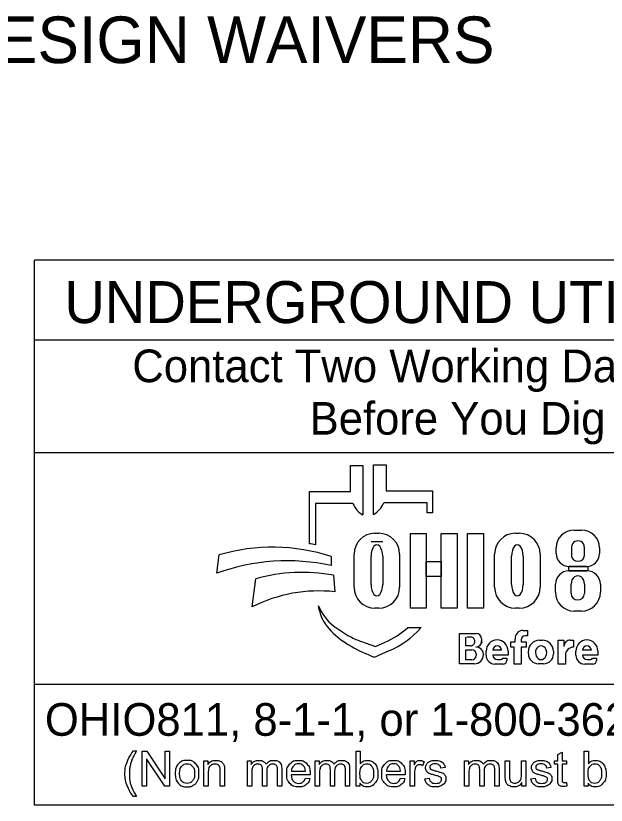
# Model space of a CAD drawing. Extents: x -10.5 to 40.6, y -3.2 to 22.
# Drawn here: x 2.897 to 5.431, y 2.143 to 5.529 of the extents above; entities that cross this region are included whole.
import ezdxf

# ---------------------------------------------------------------- set-up
doc = ezdxf.new("R2010")
doc.units = 0
doc.layers.add('SH_Data', color=7, linetype='Continuous')
doc.layers.add('SH_Text', color=7, linetype='Continuous')

msp = doc.modelspace()

# ---------------------------------------------------------------- linework, layer by layer
at = {"layer": 'SH_Data'}
for p, q in [((2.9775, 2.1428), (2.9775, 4.4803)), ((7.2275, 4.4803), (2.9775, 4.4803)), ((2.9775, 4.1387), (7.2275, 4.1387)), ((2.9775, 3.6553), (7.2275, 3.6553)), ((7.2275, 2.6607), (2.9775, 2.6607)), ((7.2275, 2.1428), (2.9775, 2.1428))]:
    msp.add_line(p, q, dxfattribs=at)
at = {"layer": 'SH_Text'}
for p, q in [((4.3335, 3.4883), (4.3335, 3.5998)), ((4.3335, 3.5998), (4.3872, 3.5998)), ((4.3872, 3.5998), (4.3872, 3.3877)), ((4.4329, 3.39), (4.4329, 3.6021)), ((4.4329, 3.6021), (4.4865, 3.6021)), ((4.4865, 3.6021), (4.4865, 3.4906)), ((4.1576, 3.2644), (4.1576, 3.4883)), ((4.1576, 3.4883), (4.3335, 3.4883)), ((4.4865, 3.4906), (4.6857, 3.4906)), ((4.6857, 3.4906), (4.6857, 3.3968)), ((4.1828, 3.4369), (4.1828, 3.26)), ((4.3439, 3.4369), (4.1828, 3.4369)), ((4.6625, 3.4392), (4.4761, 3.4392)), ((4.6625, 3.3968), (4.6625, 3.4392)), ((4.6857, 3.3968), (4.6625, 3.3968)), ((5.2931, 3.3231), (5.3258, 3.3231)), ((4.4385, 3.3091), (4.4551, 3.3091)), ((5.0416, 3.3091), (5.0581, 3.3091)), ((4.4718, 3.2721), (4.422, 3.2721)), ((5.283, 3.2111), (5.283, 3.2504)), ((5.3371, 3.2504), (5.3371, 3.2111)), ((4.3491, 3.0776), (4.3491, 3.2196)), ((4.5445, 3.2196), (4.5445, 3.0776)), ((4.9521, 3.0776), (4.9521, 3.2196)), ((5.1476, 3.2196), (5.1476, 3.0776)), ((5.2168, 3.2225), (5.2168, 3.2468)), ((5.4022, 3.2468), (5.4022, 3.2225)), ((3.7602, 3.1381), (3.7696, 3.2162)), ((4.2509, 3.2097), (4.2509, 3.1709)), ((4.422, 3.089), (4.422, 3.2114)), ((4.4718, 3.2114), (4.4718, 3.089)), ((5.025, 3.089), (5.025, 3.2114)), ((5.0748, 3.2114), (5.0748, 3.089)), ((5.3462, 3.1665), (5.2728, 3.1665)), ((4.2608, 3.1291), (4.2671, 3.0582)), ((5.271, 3.1482), (5.3483, 3.1482)), ((3.912, 2.9936), (3.9267, 3.1137)), ((5.2131, 3.0563), (5.2131, 3.0903)), ((5.2806, 3.0503), (5.2806, 3.0912)), ((5.3374, 3.0912), (5.3374, 3.0503)), ((5.4062, 3.0903), (5.4062, 3.0563)), ((4.1997, 2.9807), (4.1967, 2.9986)), ((4.4551, 2.9882), (4.4385, 2.9882)), ((5.0581, 2.9882), (5.0416, 2.9882)), ((5.3252, 2.9753), (5.2941, 2.9753)), ((4.58, 2.9048), (4.6375, 2.9048)), ((4.8013, 2.749), (4.8013, 2.8798)), ((4.8013, 2.8798), (4.8725, 2.8798)), ((5.0739, 2.8926), (5.0934, 2.8926)), ((5.0934, 2.8926), (5.0934, 2.8696)), ((4.3816, 2.8444), (4.441, 2.8239)), ((4.8293, 2.8263), (4.8293, 2.8632)), ((4.8545, 2.8632), (4.8332, 2.8632)), ((4.8963, 2.856), (4.8963, 2.8481)), ((5.0213, 2.8212), (5.0213, 2.8442)), ((5.0213, 2.8442), (5.0406, 2.8442)), ((5.0406, 2.8442), (5.0406, 2.8546)), ((5.0667, 2.8526), (5.0667, 2.8442)), ((5.0667, 2.8442), (5.0883, 2.8442)), ((5.0934, 2.8691), (5.0832, 2.8691)), ((5.0883, 2.8442), (5.0883, 2.8212)), ((5.1451, 2.8508), (5.1573, 2.8508)), ((5.2254, 2.7478), (5.2254, 2.8505)), ((5.2254, 2.8505), (5.2499, 2.8505)), ((5.2499, 2.8505), (5.2499, 2.8237)), ((5.2772, 2.8505), (5.291, 2.8505)), ((5.291, 2.8505), (5.291, 2.8209)), ((4.441, 2.8239), (4.4821, 2.8417)), ((4.8487, 2.8263), (4.8293, 2.8263)), ((5.0362, 2.8212), (5.0213, 2.8212)), ((5.0362, 2.7478), (5.0362, 2.8212)), ((5.0883, 2.8212), (5.0667, 2.8212)), ((5.0667, 2.8212), (5.0667, 2.7478)), ((4.435, 2.7769), (4.3976, 2.7934)), ((4.4983, 2.8044), (4.435, 2.7769)), ((4.8293, 2.7669), (4.8293, 2.8097)), ((4.8293, 2.8097), (4.8548, 2.8097)), ((4.8729, 2.7916), (4.8729, 2.7853)), ((4.9043, 2.7887), (4.9043, 2.7884)), ((4.9159, 2.7858), (4.9159, 2.8042)), ((4.9824, 2.8082), (4.9439, 2.8082)), ((5.0104, 2.7866), (4.944, 2.7866)), ((5.0104, 2.8042), (5.0104, 2.7866)), ((5.0973, 2.7922), (5.0973, 2.8029)), ((5.2051, 2.8029), (5.2051, 2.7922)), ((5.2559, 2.786), (5.2559, 2.7478)), ((5.3008, 2.7858), (5.3008, 2.8042)), ((5.3674, 2.8082), (5.3288, 2.8082)), ((5.3953, 2.7866), (5.3289, 2.7866)), ((5.3953, 2.8042), (5.3953, 2.7866)), ((4.865, 2.749), (4.8013, 2.749)), ((4.8546, 2.7669), (4.8293, 2.7669)), ((4.9892, 2.7478), (4.9538, 2.7478)), ((4.9649, 2.7673), (4.979, 2.7673)), ((4.9876, 2.7729), (5.0045, 2.7729)), ((5.0045, 2.7729), (5.0045, 2.7631)), ((5.0667, 2.7478), (5.0362, 2.7478)), ((5.1623, 2.7494), (5.1401, 2.7494)), ((5.2559, 2.7478), (5.2254, 2.7478)), ((5.3742, 2.7478), (5.3388, 2.7478)), ((5.3498, 2.7673), (5.3639, 2.7673)), ((5.3725, 2.7729), (5.3894, 2.7729)), ((5.3894, 2.7729), (5.3894, 2.7631))]:
    msp.add_line(p, q, dxfattribs=at)
for points in [[(4.591, 3.3081), (4.6589, 3.3081), (4.6589, 2.9881), (4.591, 2.9881)], [(4.7231, 3.3081), (4.7911, 3.3081), (4.7911, 2.9881), (4.7231, 2.9881)], [(4.8364, 3.3081), (4.9052, 3.3081), (4.9052, 2.9881), (4.8364, 2.9881)], [(4.6589, 3.1882), (4.7231, 3.1882), (4.7231, 3.1242), (4.6589, 3.1242)], [(5.2706, 3.1665), (5.3523, 3.1665), (5.3523, 3.1481), (5.2706, 3.1481)]]:
    msp.add_lwpolyline(points, close=True, dxfattribs=at)
for points in [[(3.4021, 2.3766), (3.4153, 2.3766)], [(3.4389, 2.2239), (3.4389, 2.3741), (3.4592, 2.3741), (3.5382, 2.2561), (3.5382, 2.3741), (3.5572, 2.3741), (3.5572, 2.2239), (3.5369, 2.2239), (3.4579, 2.3419), (3.4579, 2.2239), (3.4389, 2.2239)], [(4.3743, 2.2239), (4.3573, 2.2239), (4.3573, 2.3741), (4.3757, 2.3741), (4.3757, 2.3206)], [(5.2233, 2.2558), (5.2233, 2.3185), (5.2097, 2.3185), (5.2097, 2.3328), (5.2233, 2.3328), (5.2233, 2.3597), (5.2417, 2.3708), (5.2417, 2.3328), (5.2601, 2.3328), (5.2601, 2.3185), (5.2417, 2.3185), (5.2417, 2.2547)], [(5.3534, 2.2239), (5.3363, 2.2239), (5.3363, 2.3741), (5.3548, 2.3741), (5.3548, 2.3206)], [(3.7048, 2.2239), (3.7048, 2.3328), (3.7214, 2.3328), (3.7214, 2.3173)], [(3.8912, 2.2239), (3.8912, 2.3328), (3.9077, 2.3328), (3.9077, 2.3174)], [(4.1826, 2.2239), (4.1826, 2.3328), (4.1991, 2.3328), (4.1991, 2.3174)], [(4.5904, 2.2239), (4.5904, 2.3328), (4.607, 2.3328), (4.607, 2.3163)], [(4.6495, 2.3293), (4.643, 2.3122)], [(4.7394, 2.3046), (4.7213, 2.3022)], [(4.8236, 2.2239), (4.8236, 2.3328), (4.8401, 2.3328), (4.8401, 2.3174)], [(4.9979, 2.2654), (4.9979, 2.3328), (5.0164, 2.3328), (5.0164, 2.2724)], [(5.0676, 2.2745), (5.0676, 2.3328), (5.0861, 2.3328), (5.0861, 2.2239), (5.0696, 2.2239)], [(5.194, 2.3046), (5.1759, 2.3022)], [(3.7233, 2.2833), (3.7233, 2.2239), (3.7048, 2.2239)], [(3.7932, 2.2908), (3.7932, 2.2239), (3.7748, 2.2239), (3.7748, 2.2901)], [(3.9097, 2.2803), (3.9097, 2.2239), (3.8912, 2.2239)], [(3.9743, 2.2871), (3.9743, 2.2239), (3.9559, 2.2239), (3.9559, 2.2946)], [(4.0388, 2.2986), (4.0388, 2.2239), (4.0203, 2.2239), (4.0203, 2.2924)], [(4.16, 2.2736), (4.0788, 2.2736)], [(4.0799, 2.2887), (4.1406, 2.2887)], [(4.201, 2.2803), (4.201, 2.2239), (4.1826, 2.2239)], [(4.2657, 2.2871), (4.2657, 2.2239), (4.2473, 2.2239), (4.2473, 2.2946)], [(4.3301, 2.2986), (4.3301, 2.2239), (4.3117, 2.2239), (4.3117, 2.2924)], [(4.568, 2.2736), (4.4868, 2.2736)], [(4.4879, 2.2887), (4.5486, 2.2887)], [(4.6088, 2.2809), (4.6088, 2.2239), (4.5904, 2.2239)], [(4.842, 2.2803), (4.842, 2.2239), (4.8236, 2.2239)], [(4.9067, 2.2871), (4.9067, 2.2239), (4.8883, 2.2239), (4.8883, 2.2946)], [(4.9711, 2.2986), (4.9711, 2.2239), (4.9527, 2.2239), (4.9527, 2.2924)], [(4.1404, 2.2591), (4.1595, 2.2567)], [(4.3743, 2.2375), (4.3743, 2.2239)], [(4.5484, 2.2591), (4.5675, 2.2567)], [(4.653, 2.2564), (4.6712, 2.2593)], [(5.0696, 2.2239), (5.0696, 2.24)], [(5.1076, 2.2564), (5.1258, 2.2593)], [(5.2601, 2.2404), (5.2628, 2.2241)], [(5.3534, 2.2375), (5.3534, 2.2239)], [(3.4153, 2.1798), (3.4021, 2.1798)]]:
    msp.add_lwpolyline(points, dxfattribs=at)
for centre, radius, start, end in [((4.4353, 3.4736), 0.0985, 201.9296, 240.7469), ((4.3847, 3.476), 0.0985, 299.2531, 338.0704), ((5.2931, 3.2468), 0.0763, 90, 180), ((5.3258, 3.2468), 0.0763, 0, 90), ((4.4385, 3.2196), 0.0895, 90, 180), ((4.4551, 3.2196), 0.0895, 0, 90), ((5.0416, 3.2196), 0.0895, 90, 180), ((5.0581, 3.2196), 0.0895, 0, 90), ((4.0295, 2.4554), 0.8191, 79.2074, 81.0007), ((3.9997, 2.4302), 0.8191, 72.1402, 106.3144), ((5.2728, 3.2225), 0.056, 180, 270), ((5.3462, 3.2225), 0.056, 270, 0), ((4.0628, 2.2991), 0.8919, 77.8238, 109.8274), ((4.1267, 2.4094), 0.7322, 79.44, 105.8467), ((5.271, 3.0903), 0.0579, 90, 180), ((5.3483, 3.0903), 0.0579, 0, 90), ((4.1987, 2.4262), 0.6357, 83.8248, 116.8021), ((4.4385, 3.0776), 0.0895, 180, 270), ((4.4551, 3.0776), 0.0895, 270, 0), ((5.0416, 3.0776), 0.0895, 180, 270), ((5.0581, 3.0776), 0.0895, 270, 0), ((5.2941, 3.0563), 0.081, 180, 270), ((5.3252, 3.0563), 0.081, 270, 0), ((4.3841, 3.0707), 0.2008, 201.0457, 232.5314), ((4.341, 3.0048), 0.1433, 189.6817, 216.0884), ((4.4747, 3.1022), 0.3088, 216.0884, 235.7167), ((4.5766, 3.3219), 0.5173, 232.5314, 241.794), ((4.3387, 3.1722), 0.3602, 293.4582, 312.0712), ((4.3387, 3.1722), 0.401, 293.4582, 317.8286), ((4.8725, 2.856), 0.0238, 0, 90), ((5.0739, 2.859), 0.0335, 90, 187.5187), ((4.6412, 3.3465), 0.6044, 235.7167, 246.2325), ((4.4914, 3.1631), 0.3371, 241.794, 250.9821), ((4.8487, 2.845), 0.0187, 270, 2.0582), ((4.8505, 2.8463), 0.0169, 357.8325, 90), ((4.8721, 2.8453), 0.0243, 270, 6.6529), ((4.9631, 2.8042), 0.0473, 0, 180), ((5.0832, 2.8526), 0.0165, 90, 180), ((5.1451, 2.8029), 0.0478, 90, 180), ((5.1573, 2.8029), 0.0478, 0, 90), ((5.2768, 2.8237), 0.0269, 89.2449, 180), ((5.3481, 2.8042), 0.0473, 0, 180), ((4.8722, 2.7889), 0.0321, 4.0748, 90), ((4.8827, 2.8438), 0.0175, 347.4023, 0), ((4.9632, 2.8072), 0.0193, 2.9632, 177.0368), ((5.2908, 2.786), 0.0349, 89.6033, 180), ((5.3481, 2.8072), 0.0193, 2.9632, 177.0368), ((4.8546, 2.7853), 0.0184, 270, 0), ((4.8548, 2.7916), 0.0181, 0, 90), ((4.865, 2.7884), 0.0393, 270, 0), ((4.8714, 2.7887), 0.033, 0, 11.7502), ((4.9538, 2.7858), 0.038, 180, 270), ((4.9649, 2.7883), 0.021, 184.827, 270), ((5.1401, 2.7922), 0.0428, 180, 270), ((5.1623, 2.7922), 0.0428, 270, 0), ((5.3388, 2.7858), 0.038, 180, 270), ((5.3498, 2.7883), 0.021, 184.827, 270), ((4.979, 2.7767), 0.00938, 270, 335.9979), ((4.9892, 2.7631), 0.0152, 270, 0), ((5.3639, 2.7767), 0.00938, 270, 335.9979), ((5.3742, 2.7631), 0.0152, 270, 0)]:
    msp.add_arc(centre, radius, start, end, dxfattribs=at)
for centre, major_axis, ratio, start_param, end_param in [((4.4469, 3.2114), (0, 0.0484), 0.514403, 4.712389, 7.853982), ((5.0499, 3.2114), (0, 0.0484), 0.514403, 4.712389, 7.853982), ((5.31, 3.2504), (0.0271, 0), 0.969373, 0, 3.141593), ((5.31, 3.2111), (0.0271, 0), 0.818453, 3.141593, 6.283185), ((5.309, 3.0912), (0, 0.0358), 0.794529, 4.712389, 7.853982), ((4.4469, 3.089), (0, 0.0484), 0.514403, 1.570796, 4.712389), ((5.0499, 3.089), (0, 0.0484), 0.514403, 1.570796, 4.712389), ((5.309, 3.0503), (0.0284, 0), 0.959837, 3.141593, 6.283185), ((5.1517, 2.7976), (0, 0.029), 0.832186, 4.712389, 7.853982), ((5.1517, 2.7976), (0, 0.0302), 0.797287, 1.570796, 4.712389)]:
    msp.add_ellipse(centre, major_axis=major_axis, ratio=ratio, start_param=start_param, end_param=end_param, dxfattribs=at)
for points in [[(3.4021, 2.1798), (3.3869, 2.199), (3.3763, 2.2248), (3.3657, 2.2506), (3.3657, 2.2783), (3.3657, 2.3026), (3.3736, 2.325), (3.3829, 2.3509), (3.4021, 2.3766)], [(3.4153, 2.3766), (3.4029, 2.3553), (3.3989, 2.3462), (3.3927, 2.332), (3.3891, 2.3167), (3.3847, 2.2975), (3.3847, 2.2782), (3.3847, 2.2289), (3.4153, 2.1798)], [(3.5814, 2.2783), (3.5814, 2.3085), (3.5981, 2.3231), (3.6122, 2.3352), (3.6323, 2.3352), (3.6547, 2.3352), (3.669, 2.3205), (3.6832, 2.3058), (3.6832, 2.2799), (3.6832, 2.2589), (3.6769, 2.2469), (3.6706, 2.2348), (3.6586, 2.2282), (3.6466, 2.2215), (3.6323, 2.2215), (3.6095, 2.2215), (3.5954, 2.2362), (3.5814, 2.2508), (3.5814, 2.2783)], [(3.6003, 2.2783), (3.6003, 2.2574), (3.6094, 2.247), (3.6185, 2.2366), (3.6323, 2.2366), (3.646, 2.2366), (3.6551, 2.2471), (3.6642, 2.2575), (3.6642, 2.279), (3.6642, 2.2991), (3.6551, 2.3095), (3.6459, 2.3199), (3.6323, 2.3199), (3.6185, 2.3199), (3.6094, 2.3096), (3.6003, 2.2992), (3.6003, 2.2783)], [(3.7214, 2.3173), (3.7334, 2.3352), (3.756, 2.3352), (3.7659, 2.3352), (3.7741, 2.3316), (3.7823, 2.3281), (3.7864, 2.3224), (3.7905, 2.3166), (3.7922, 2.3087), (3.7932, 2.3036), (3.7932, 2.2908)], [(3.7748, 2.2901), (3.7748, 2.3013), (3.7726, 2.3069), (3.7705, 2.3125), (3.765, 2.3158), (3.7595, 2.3191), (3.7521, 2.3191), (3.7404, 2.3191), (3.7318, 2.3117), (3.7233, 2.3042), (3.7233, 2.2833)], [(3.9077, 2.3174), (3.9128, 2.3254), (3.9214, 2.3303), (3.9299, 2.3352), (3.9407, 2.3352), (3.9528, 2.3352), (3.9606, 2.3301), (3.9683, 2.3251), (3.9715, 2.3161), (3.9844, 2.3352), (4.0051, 2.3352), (4.0213, 2.3352), (4.03, 2.3262), (4.0388, 2.3172), (4.0388, 2.2986)], [(3.9559, 2.2946), (3.9559, 2.3069), (3.9514, 2.313), (3.9469, 2.3191), (3.9366, 2.3191), (3.9288, 2.3191), (3.9222, 2.315), (3.9156, 2.311), (3.9126, 2.3031), (3.9097, 2.2952), (3.9097, 2.2803)], [(4.0203, 2.2924), (4.0203, 2.3035), (4.0185, 2.3083), (4.0168, 2.3132), (4.012, 2.3162), (4.0073, 2.3191), (4.001, 2.3191), (3.9895, 2.3191), (3.9819, 2.3115), (3.9743, 2.3039), (3.9743, 2.2871)], [(4.1595, 2.2567), (4.155, 2.24), (4.1428, 2.2307), (4.1306, 2.2215), (4.1117, 2.2215), (4.0878, 2.2215), (4.0738, 2.2362), (4.0598, 2.2509), (4.0598, 2.2774), (4.0598, 2.3049), (4.074, 2.32), (4.0881, 2.3352), (4.1106, 2.3352), (4.1324, 2.3352), (4.1463, 2.3203), (4.1601, 2.3055), (4.1601, 2.2785), (4.1601, 2.2769), (4.16, 2.2736)], [(4.1406, 2.2887), (4.1394, 2.3025), (4.1337, 2.3094), (4.1249, 2.3201), (4.1108, 2.3201), (4.0981, 2.3201), (4.0894, 2.3115), (4.0808, 2.303), (4.0799, 2.2887)], [(4.1991, 2.3174), (4.2042, 2.3254), (4.2127, 2.3303), (4.2212, 2.3352), (4.2321, 2.3352), (4.2442, 2.3352), (4.2519, 2.3301), (4.2597, 2.3251), (4.2628, 2.3161), (4.2758, 2.3352), (4.2965, 2.3352), (4.3127, 2.3352), (4.3214, 2.3262), (4.3301, 2.3172), (4.3301, 2.2986)], [(4.2473, 2.2946), (4.2473, 2.3069), (4.2428, 2.313), (4.2383, 2.3191), (4.228, 2.3191), (4.2202, 2.3191), (4.2136, 2.315), (4.207, 2.311), (4.204, 2.3031), (4.201, 2.2952), (4.201, 2.2803)], [(4.3117, 2.2924), (4.3117, 2.3035), (4.3099, 2.3083), (4.3081, 2.3132), (4.3034, 2.3162), (4.2987, 2.3191), (4.2923, 2.3191), (4.2809, 2.3191), (4.2733, 2.3115), (4.2657, 2.3039), (4.2657, 2.2871)], [(4.3741, 2.2792), (4.3741, 2.2596), (4.3794, 2.2509), (4.3881, 2.2366), (4.4029, 2.2366), (4.415, 2.2366), (4.4238, 2.2471), (4.4326, 2.2576), (4.4326, 2.2784), (4.4326, 2.2998), (4.4241, 2.3099), (4.4157, 2.3201), (4.4038, 2.3201), (4.3917, 2.3201), (4.3829, 2.3096), (4.3741, 2.299), (4.3741, 2.2792)], [(4.3757, 2.3206), (4.3874, 2.3352), (4.4055, 2.3352), (4.4155, 2.3352), (4.4245, 2.3311), (4.4335, 2.3271), (4.4392, 2.3198), (4.445, 2.3124), (4.4483, 2.3021), (4.4516, 2.2918), (4.4516, 2.28), (4.4516, 2.252), (4.4378, 2.2368), (4.4239, 2.2215), (4.4046, 2.2215), (4.3853, 2.2215), (4.3743, 2.2375)], [(4.5675, 2.2567), (4.563, 2.24), (4.5508, 2.2307), (4.5386, 2.2215), (4.5196, 2.2215), (4.4958, 2.2215), (4.4818, 2.2362), (4.4678, 2.2509), (4.4678, 2.2774), (4.4678, 2.3049), (4.482, 2.32), (4.4961, 2.3352), (4.5186, 2.3352), (4.5404, 2.3352), (4.5543, 2.3203), (4.5681, 2.3055), (4.5681, 2.2785), (4.5681, 2.2769), (4.568, 2.2736)], [(4.5486, 2.2887), (4.5474, 2.3025), (4.5417, 2.3094), (4.5328, 2.3201), (4.5188, 2.3201), (4.5061, 2.3201), (4.4974, 2.3115), (4.4888, 2.303), (4.4879, 2.2887)], [(4.607, 2.3163), (4.6133, 2.3278), (4.6187, 2.3315), (4.6241, 2.3352), (4.6305, 2.3352), (4.6398, 2.3352), (4.6495, 2.3293)], [(4.643, 2.3122), (4.6363, 2.3162), (4.6295, 2.3162), (4.6235, 2.3162), (4.6187, 2.3125), (4.6139, 2.3089), (4.6119, 2.3024), (4.6088, 2.2926), (4.6088, 2.2809)], [(4.7213, 2.3022), (4.7201, 2.3106), (4.7142, 2.3153), (4.7083, 2.3201), (4.6975, 2.3201), (4.6848, 2.3201), (4.6794, 2.3159), (4.6739, 2.3116), (4.6739, 2.306), (4.6739, 2.3024), (4.6762, 2.2995), (4.6785, 2.2966), (4.6833, 2.2946), (4.686, 2.2936), (4.6996, 2.2899), (4.7192, 2.2847), (4.7269, 2.2813), (4.7347, 2.278), (4.7391, 2.2717), (4.7435, 2.2653), (4.7435, 2.2559), (4.7435, 2.2467), (4.7381, 2.2386), (4.7327, 2.2304), (4.7226, 2.226), (4.7124, 2.2215), (4.6996, 2.2215), (4.6784, 2.2215), (4.6672, 2.2303), (4.6561, 2.2391), (4.653, 2.2564)], [(4.6712, 2.2593), (4.6727, 2.2483), (4.6798, 2.2425), (4.6868, 2.2366), (4.6995, 2.2366), (4.7122, 2.2366), (4.7184, 2.2418), (4.7245, 2.247), (4.7245, 2.254), (4.7245, 2.2602), (4.7191, 2.2638), (4.7153, 2.2663), (4.7002, 2.2701), (4.6799, 2.2752), (4.672, 2.2789), (4.6642, 2.2827), (4.6601, 2.2893), (4.6561, 2.2959), (4.6561, 2.3038), (4.6561, 2.3111), (4.6594, 2.3173), (4.6628, 2.3235), (4.6685, 2.3276), (4.6728, 2.3308), (4.6803, 2.333), (4.6877, 2.3352), (4.6962, 2.3352), (4.709, 2.3352), (4.7187, 2.3315), (4.7284, 2.3278), (4.733, 2.3215), (4.7377, 2.3152), (4.7394, 2.3046)], [(4.8401, 2.3174), (4.8452, 2.3254), (4.8537, 2.3303), (4.8622, 2.3352), (4.8731, 2.3352), (4.8852, 2.3352), (4.8929, 2.3301), (4.9007, 2.3251), (4.9038, 2.3161), (4.9168, 2.3352), (4.9375, 2.3352), (4.9537, 2.3352), (4.9624, 2.3262), (4.9711, 2.3172), (4.9711, 2.2986)], [(4.8883, 2.2946), (4.8883, 2.3069), (4.8838, 2.313), (4.8793, 2.3191), (4.869, 2.3191), (4.8612, 2.3191), (4.8546, 2.315), (4.848, 2.311), (4.845, 2.3031), (4.842, 2.2952), (4.842, 2.2803)], [(4.9527, 2.2924), (4.9527, 2.3035), (4.9509, 2.3083), (4.9491, 2.3132), (4.9444, 2.3162), (4.9397, 2.3191), (4.9333, 2.3191), (4.9219, 2.3191), (4.9143, 2.3115), (4.9067, 2.3039), (4.9067, 2.2871)], [(5.1759, 2.3022), (5.1747, 2.3106), (5.1688, 2.3153), (5.1629, 2.3201), (5.1521, 2.3201), (5.1394, 2.3201), (5.1339, 2.3159), (5.1285, 2.3116), (5.1285, 2.306), (5.1285, 2.3024), (5.1308, 2.2995), (5.133, 2.2966), (5.1378, 2.2946), (5.1406, 2.2936), (5.1542, 2.2899), (5.1737, 2.2847), (5.1815, 2.2813), (5.1893, 2.278), (5.1937, 2.2717), (5.1981, 2.2653), (5.1981, 2.2559), (5.1981, 2.2467), (5.1927, 2.2386), (5.1873, 2.2304), (5.1772, 2.226), (5.167, 2.2215), (5.1542, 2.2215), (5.1329, 2.2215), (5.1218, 2.2303), (5.1107, 2.2391), (5.1076, 2.2564)], [(5.1258, 2.2593), (5.1273, 2.2483), (5.1343, 2.2425), (5.1414, 2.2366), (5.154, 2.2366), (5.1668, 2.2366), (5.1729, 2.2418), (5.1791, 2.247), (5.1791, 2.254), (5.1791, 2.2602), (5.1736, 2.2638), (5.1698, 2.2663), (5.1548, 2.2701), (5.1345, 2.2752), (5.1266, 2.2789), (5.1188, 2.2827), (5.1147, 2.2893), (5.1107, 2.2959), (5.1107, 2.3038), (5.1107, 2.3111), (5.114, 2.3173), (5.1173, 2.3235), (5.1231, 2.3276), (5.1274, 2.3308), (5.1348, 2.333), (5.1423, 2.3352), (5.1508, 2.3352), (5.1636, 2.3352), (5.1733, 2.3315), (5.183, 2.3278), (5.1876, 2.3215), (5.1922, 2.3152), (5.194, 2.3046)], [(5.3532, 2.2792), (5.3532, 2.2596), (5.3585, 2.2509), (5.3672, 2.2366), (5.382, 2.2366), (5.3941, 2.2366), (5.4029, 2.2471), (5.4116, 2.2576), (5.4116, 2.2784), (5.4116, 2.2998), (5.4032, 2.3099), (5.3948, 2.3201), (5.3828, 2.3201), (5.3708, 2.3201), (5.362, 2.3096), (5.3532, 2.299), (5.3532, 2.2792)], [(5.3548, 2.3206), (5.3664, 2.3352), (5.3846, 2.3352), (5.3946, 2.3352), (5.4036, 2.3311), (5.4125, 2.3271), (5.4183, 2.3198), (5.4241, 2.3124), (5.4274, 2.3021), (5.4306, 2.2918), (5.4306, 2.28), (5.4306, 2.252), (5.4168, 2.2368), (5.403, 2.2215), (5.3836, 2.2215), (5.3644, 2.2215), (5.3534, 2.2375)], [(4.0788, 2.2736), (4.0799, 2.2557), (4.089, 2.2462), (4.0981, 2.2366), (4.1117, 2.2366), (4.1219, 2.2366), (4.1291, 2.242), (4.1362, 2.2473), (4.1404, 2.2591)], [(4.4868, 2.2736), (4.4879, 2.2557), (4.497, 2.2462), (4.5061, 2.2366), (4.5197, 2.2366), (4.5299, 2.2366), (4.537, 2.242), (4.5442, 2.2473), (4.5484, 2.2591)], [(5.0164, 2.2724), (5.0164, 2.258), (5.0175, 2.253), (5.0192, 2.2457), (5.0249, 2.2416), (5.0305, 2.2374), (5.0388, 2.2374), (5.0471, 2.2374), (5.0543, 2.2417), (5.0616, 2.2459), (5.0646, 2.2533), (5.0676, 2.2606), (5.0676, 2.2745)], [(5.0696, 2.24), (5.0569, 2.2215), (5.0351, 2.2215), (5.0255, 2.2215), (5.0171, 2.2252), (5.0088, 2.2289), (5.0047, 2.2345), (5.0007, 2.2401), (4.9991, 2.2482), (4.9979, 2.2536), (4.9979, 2.2654)], [(5.2628, 2.2241), (5.255, 2.2224), (5.2488, 2.2224), (5.2388, 2.2224), (5.2333, 2.2256), (5.2278, 2.2288), (5.2255, 2.234), (5.2233, 2.2392), (5.2233, 2.2558)], [(5.2417, 2.2547), (5.2417, 2.2468), (5.2427, 2.2445), (5.2436, 2.2423), (5.2458, 2.2409), (5.248, 2.2396), (5.2521, 2.2396), (5.2551, 2.2396), (5.2601, 2.2404)]]:
    msp.add_open_spline(points, degree=3, dxfattribs=at)

# ---------------------------------------------------------------- texts
for s, height, p in [('ADA DESIGN WAIVERS', 0.2, (1.9944, 5.3256)), ('UNDERGROUND UTILITIES', 0.18, (3.1057, 4.2106)), ('Contact Two Working Days', 0.14, (3.3972, 3.9571)), ('Before You Dig', 0.14, (4.1583, 3.7321)), ('OHIO811, 8-1-1, or 1-800-362-2764', 0.14, (3.022, 2.4406))]:
    msp.add_text(s, height=height, dxfattribs=at).set_placement(p)

doc.saveas('drawing.dxf')
